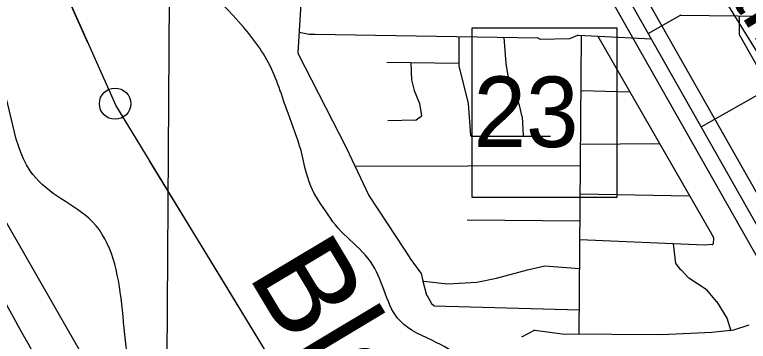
# Model space of a CAD drawing. Extents: x 408847 to 817539, y 923858 to 1151780.
# Drawn here: x 498494 to 503168, y 1025796 to 1027880 of the extents above; entities that cross this region are included whole.
import ezdxf

# ---------------------------------------------------------------- set-up
doc = ezdxf.new("R2010")
doc.units = 0
for name, color, linetype in [('Lakes and Ponds', 7, 'Continuous'), ('Level 12', 7, 'Continuous'), ('Level 39', 7, 'Continuous'), ('Level 42', 7, 'Continuous'), ('Level 43', 7, 'Continuous'), ('Level 6', 7, 'Continuous'), ('Local Roads Paved', 7, 'Continuous'), ('Masks for Text', 7, 'Continuous'), ('Narrow River Creek and Branch and Slough', 7, 'Continuous'), ('Section Lines', 7, 'Continuous'), ('US Highways Related Text', 7, 'Continuous'), ('US Routes Highway Center Lines', 7, 'Continuous')]:
    doc.layers.add(name, color=color, linetype=linetype)

msp = doc.modelspace()

# ---------------------------------------------------------------- linework, layer by layer
at = {"layer": 'Lakes and Ponds'}
for points in [[(493694.7, 1035268.7), (494345.1, 1033520.9), (495237.6, 1031768.9), (496248.3, 1030020.8), (497258.9, 1028150.4), (498297.4, 1026290), (499282, 1024487.8), (500258.5, 1022571.4), (500988.9, 1020781.5), (501691.1, 1018901.5), (502255.4, 1017147.8), (502705.7, 1015476.5), (502819.2, 1015003.5)], [(503148.6, 1015080.5), (503028.5, 1015856.8), (502983.5, 1016698.2), (502949.2, 1016993.6), (502812, 1017176.4), (502784.2, 1017429.7), (502742.9, 1017978.7), (502273.1, 1018514.2), (502177.4, 1018830.8), (502395.5, 1018764.4), (502829.9, 1018796), (502940.3, 1019000.2), (502840.3, 1019048.4), (502764.5, 1019268.9), (502853.1, 1019705.5), (502779.2, 1019809.8), (502753.3, 1019916), (502781.7, 1020250.5), (502427.7, 1020491.3), (502107.3, 1020415.6), (501933.4, 1020574.1), (501829.3, 1020544.1), (501727.3, 1020632.4), (501737.4, 1020736.6), (501743.7, 1020944.9), (501429.5, 1020971.3), (501371.7, 1021181.7), (501478, 1021386), (500940.3, 1021971.6), (500317.8, 1023619.1), (500380.3, 1023959.6), (500682.9, 1024241.8), (500573.3, 1024688.6), (500371.3, 1024809.1), (500423.1, 1024598.7), (500511.1, 1024494.4), (500534.8, 1024282), (500430.6, 1024198), (500006.3, 1024256.6), (499822.4, 1024419.1), (499432.9, 1025116.7), (499265.2, 1025467.5), (498966.3, 1026581.7), (498764.4, 1026722.2), (498592.4, 1026884.7), (498347, 1027552.1), (498057.1, 1027840.9), (497881.5, 1028259.9), (497422.1, 1029035.7), (497464.4, 1029252), (496986.6, 1029757.4), (496912.7, 1029865.7), (496833.1, 1030216.4), (497051.3, 1030284.3), (497093.2, 1030184), (497293.6, 1030338.1), (497367.5, 1030219.8), (497292.7, 1029584.8), (497394.8, 1029610.7), (497543.6, 1030169.5), (497495.8, 1030383.9), (497387.8, 1030466.2), (497498.2, 1030678.4), (497167.7, 1030530.6), (497063.6, 1030466.6), (496629.2, 1030501.1), (496153.5, 1031018.6), (495708, 1031702.2), (495414.4, 1032275.6), (495553.1, 1032718.2), (495763.3, 1032788), (495833.5, 1032902.1), (495825.8, 1033112.5), (495741.9, 1033218.8), (495433.8, 1033347.4), (494997.3, 1033239.7), (494957.4, 1033343.9), (495023.6, 1033454), (495444, 1033515.6), (495520.2, 1033617.7), (495496.3, 1033717.9), (495424.4, 1033830.2), (495318.3, 1033826.3), (495151.8, 1033608.1), (494845.5, 1033550.4), (494963.8, 1033734.6), (494673.9, 1033979.3), (494576.3, 1034322), (494496.7, 1034775.8)], [(500490, 1026606.9), (500380.3, 1026785.5), (500318.2, 1027013.5), (500235.3, 1027251.9), (500110.9, 1027573.1), (500017.6, 1027718.2), (499424.2, 1028286.5)], [(503763.3, 1014936.1), (503704.7, 1015561.5), (503719.3, 1016034.2), (503585.8, 1016533.3), (503638.8, 1017292.5), (503816.9, 1018881), (503753.1, 1019133.5), (503708.3, 1020117.2), (503593, 1020766.4), (503593.2, 1020874.6), (503537.7, 1021323.5), (503263.7, 1021536.1), (503167.9, 1021742.6), (503158.8, 1022457.8), (502959.9, 1023539.9), (502534.3, 1024117.4), (502292.3, 1024292), (501776.5, 1024771.4), (501696.9, 1025222.2), (501507.2, 1025543), (501183.2, 1025787.8), (500949.2, 1025926.3), (500775.5, 1026283.1), (500491.6, 1026604), (500490, 1026606.9)]]:
    msp.add_spline(points, degree=3, dxfattribs=at)
at = {"layer": 'Level 12'}
msp.add_circle((499133.8, 1027312.3), 99.8, dxfattribs=at)
at = {"layer": 'Level 39'}
msp.add_lwpolyline([(501408.6, 1027795.3), (502330.7, 1027795.3), (502330.7, 1026713.6), (501408.6, 1026713.6)], close=True, dxfattribs=at)
at = {"layer": 'Level 6'}
for p, q in [((503829.2, 1025666.5), (501328.3, 1030088.7)), ((501154.2, 1029990.2), (503655.2, 1025568.1))]:
    msp.add_line(p, q, dxfattribs=at)
at = {"layer": 'Local Roads Paved'}
for p, q in [((500323.1, 1028054), (500298.1, 1027635.6)), ((502530.6, 1027759.6), (502734.9, 1027876.4)), ((502736.9, 1027876.9), (503893.5, 1027862.6)), ((503108.5, 1027872.3), (503108.6, 1027756)), ((500306, 1027768.3), (500369.3, 1027756.5)), ((500370, 1027756.4), (500405.5, 1027756.4)), ((500405.5, 1027756.4), (501827.5, 1027731.3)), ((501323, 1027740.2), (501323, 1027554.7)), ((501624.1, 1027568.8), (501612.8, 1027735.1)), ((501829.2, 1027730.9), (501841.9, 1027724.6)), ((501843.7, 1027724.1), (502028.4, 1027727.7)), ((502029.8, 1027728), (502082.1, 1027748.9)), ((502083.8, 1027749.2), (502550, 1027725.2)), ((502090, 1025843.8), (502104.5, 1027748.1)), ((502208.3, 1027742.8), (502925.1, 1026496.4)), ((503109.1, 1027754.1), (503788.4, 1026548.6)), ((500298.5, 1027633.5), (500606.2, 1027032)), ((501323, 1027568.4), (500864.3, 1027575.8)), ((501018.1, 1027573.3), (501022, 1027465)), ((501323.2, 1027553.8), (501383.9, 1027314.3)), ((501638.4, 1027490.1), (501624.2, 1027568.4)), ((501710, 1027303.5), (501638.6, 1027489.4)), ((501022.1, 1027464.2), (501039.8, 1027396.7)), ((501040, 1027396.3), (501072, 1027314.4)), ((502101.8, 1027396.5), (502411.9, 1027388.8)), ((501072.2, 1027313.6), (501086.1, 1027234)), ((501384, 1027313.6), (501398.1, 1027109.7)), ((501728, 1027228.3), (501710.2, 1027303)), ((501049.4, 1027206.4), (500871.4, 1027202.8)), ((501084.4, 1027230.1), (501051.6, 1027207.1)), ((501735.2, 1027109.6), (501728.1, 1027227.6)), ((501402, 1027106), (501907.3, 1027106)), ((500606.2, 1027032), (500749.5, 1026726.2)), ((502604, 1027055.9), (502099.2, 1027052.2)), ((502098.2, 1026916), (500663.6, 1026912.4)), ((502096.8, 1026736.7), (502793.6, 1026725.5)), ((501376.8, 1026571.7), (502095.5, 1026564.4)), ((502925.2, 1026496.4), (502946.1, 1026458)), ((502946.6, 1026455.8), (502943.4, 1026417.4)), ((502885.5, 1026410.3), (502094.6, 1026443)), ((502706.4, 1026293.1), (502690.2, 1026418.4)), ((502939.6, 1026413.7), (502885.9, 1026410.4)), ((501011.3, 1026327.8), (501082.4, 1026231.7)), ((501760.4, 1026252.6), (501870.8, 1026277.5)), ((501872, 1026277.6), (502093.2, 1026261.8)), ((502738.7, 1026252.7), (502707.2, 1026291.1)), ((501083.1, 1026230.2), (501093.6, 1026181)), ((501563.3, 1026198.8), (501760.2, 1026252.5)), ((502788.6, 1026199.1), (502738.9, 1026252.5)), ((501093.7, 1026180.7), (501118.6, 1026091.7)), ((501100.8, 1026180.8), (501251, 1026163)), ((501251.7, 1026162.9), (501437.5, 1026173.7)), ((501438, 1026173.7), (501563, 1026198.7)), ((502899.6, 1026127.4), (502789.4, 1026198.5)), ((502968, 1026048.4), (502900.4, 1026126.6)), ((501119, 1026090.8), (501147.2, 1026041.5)), ((501147.8, 1026040.6), (501164.2, 1026024.2)), ((503032.4, 1025944.6), (502968.3, 1026047.9)), ((501166.9, 1026023), (502091.2, 1025997.8)), ((503057.8, 1025861.7), (503032.8, 1025943.7)), ((503076.1, 1025869), (503172.1, 1025901)), ((501724.5, 1025825.8), (501805.8, 1025868.3)), ((501808.2, 1025868.7), (501982.3, 1025843.8)), ((501982.8, 1025843.8), (502616.8, 1025840.2)), ((502617, 1025840.2), (502935.8, 1025854.5)), ((502936, 1025854.5), (503075.2, 1025868.8))]:
    msp.add_line(p, q, dxfattribs=at)
for points in [[(502866.8, 1027165.2), (503302.1, 1027410.7), (503580.8, 1027568)], [(500749.7, 1026725.7), (500921.6, 1026464.1), (501011.2, 1026328)]]:
    msp.add_lwpolyline(points, dxfattribs=at)
for centre, start, end in [((502736.9, 1027872.9), 89.2901, 119.7573), ((500370, 1027760.4), 259.3751, 270), ((500405.5, 1027752.4), 88.9893, 90), ((501827.4, 1027727.3), 63.4234, 88.9893), ((501843.7, 1027728.1), 243.4234, 271.1023), ((502028.3, 1027731.7), 271.1023, 291.8114), ((502083.5, 1027745.2), 87.0629, 111.8114), ((503112.6, 1027756), 180.0406, 209.4019), ((500302, 1027635.3), 176.5778, 207.0964), ((501327, 1027554.7), 180, 194.2304), ((501628.1, 1027569.1), 183.8985, 190.2998), ((501642.3, 1027490.8), 190.2998, 201.0279), ((501026, 1027465.2), 182.0444, 194.7365), ((501043.7, 1027397.7), 194.7365, 201.3608), ((501068.3, 1027312.9), 9.8609, 21.3608), ((501380, 1027313.4), 3.9432, 14.2304), ((501706.3, 1027302), 13.386, 21.0279), ((501049.4, 1027210.4), 271.1463, 305.0056), ((501082.1, 1027233.3), 305.0056, 9.8609), ((501724.1, 1027227.3), 3.4665, 13.386), ((501402, 1027110), 183.9432, 270), ((500753.1, 1026727.9), 205.0947, 213.3131), ((502921.7, 1026494.4), 28.5983, 29.9038), ((502942.6, 1026456.1), 355.2387, 28.5983), ((502885.7, 1026414.3), 267.6347, 273.5781), ((502939.4, 1026417.7), 273.5781, 355.2387), ((501014.5, 1026330.2), 213.3275, 216.5151), ((501871.7, 1026273.6), 85.9123, 102.7306), ((502710.3, 1026293.6), 187.3487, 219.2753), ((501079.2, 1026229.4), 12.0889, 36.5151), ((501761.3, 1026248.7), 102.7306, 105.2624), ((502741.8, 1026255.2), 219.2753, 223.0107), ((501097.5, 1026181.8), 192.0889, 195.6348), ((501437.2, 1026177.6), 273.3035, 281.3155), ((501562.3, 1026202.7), 281.3155, 285.2624), ((502791.5, 1026201.9), 223.0107, 237.1583), ((501251.5, 1026166.9), 263.2076, 273.3035), ((502897.4, 1026124), 40.8008, 57.1583), ((501122.5, 1026092.7), 195.6348, 209.7325), ((501150.6, 1026043.4), 209.7325, 224.9856), ((502964.9, 1026045.8), 31.8145, 40.8008), ((501167, 1026027), 224.9856, 268.439), ((503029, 1025942.5), 16.9195, 31.8145), ((501807.6, 1025864.7), 81.8659, 117.5646), ((501982.8, 1025847.8), 261.8659, 269.6761), ((502935.6, 1025858.5), 272.5747, 275.8589), ((503074.8, 1025872.8), 275.8589, 288.4436), ((502616.8, 1025844.2), 269.6761, 272.5747)]:
    msp.add_arc(centre, 4, start, end, dxfattribs=at)
at = {"layer": 'Masks for Text'}
msp.add_lwpolyline([(502620.8, 1028614.6), (503287.2, 1027536.8), (503789.3, 1027838.2), (503100, 1028879.5)], close=True, dxfattribs=at)
at = {"layer": 'Narrow River Creek and Branch and Slough'}
for points in [[(503534.7, 1014999), (503019.9, 1020832.8), (502968.4, 1020987.4), (502031.5, 1022550.7), (499138.3, 1027302.2), (498232.2, 1029339.1), (498016, 1030017.6), (497882.2, 1030594.6), (497593.9, 1031181.1), (495994.9, 1033268)], [(498961.1, 1027700.6), (498605.5, 1028500.1)], [(499808.7, 1026201.3), (499353.6, 1026948.6)], [(500263.7, 1025453.9), (499808.7, 1026201.3)]]:
    msp.add_lwpolyline(points, dxfattribs=at)
at = {"layer": 'Section Lines'}
msp.add_line((499480.8, 1028230.3), (499459.6, 1025101.4), dxfattribs=at)
msp.add_lwpolyline([(499274.6, 1025098.7), (496209.7, 1030456.3)], dxfattribs=at)
at = {"layer": 'US Routes Highway Center Lines'}
msp.add_line((503742.2, 1025617.3), (501241.3, 1030039.4), dxfattribs=at)

# ---------------------------------------------------------------- texts
at = {"layer": 'Level 42'}
msp.add_text('Blackburn', height=600, rotation=300.9636, dxfattribs=at).set_placement((499973.6, 1026221))
at = {"layer": 'Level 43'}
msp.add_text('23', height=450, rotation=359.9063, dxfattribs=at).set_placement((501416.5, 1027036.1))
at = {"layer": 'US Highways Related Text'}
msp.add_text('Trail', height=450, rotation=301.5599, dxfattribs=at).set_placement((502646.3, 1028645.2))

doc.saveas('drawing.dxf')
